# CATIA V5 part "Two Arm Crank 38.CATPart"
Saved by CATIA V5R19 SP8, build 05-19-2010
Part number: Two Arm Crank 38
Bounding box of the stored display mesh (mm): x -12.5 to 12.5, y 672.86 to 718.081, z 460.504 to 507.14
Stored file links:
  G:\EU_thinkMotion\CFAO_2010\MMS_groupe3\MMS_groupe3\A reprendre\fovide\fovide\Two Arm Crank 38.CATPart
  G:\EU_thinkMotion\CFAO_2010\MMS_groupe3\MMS_groupe3\A reprendre\fovide\fovide\fovide.CATProduct
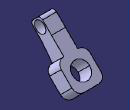
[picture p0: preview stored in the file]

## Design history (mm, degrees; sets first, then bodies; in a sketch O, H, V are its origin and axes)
Set1
  Plane1: linked copy from another document
  Point1 "Point.J": linked copy from another document
  Line1: linked copy from another document
  Line2: linked copy from another document
  Plane2: linked copy from another document
  Point2 "Point.L": linked copy from another document
Body1 (main body)
  Sketch1 on Plane1, origin (0, 590, 590), H (1, 0, 0), V (0, -0.7071, 0.7071)
    circle A1 centre (0, -162.6346) radius 7.5
    point P1 (0, -162.6346)
    reference projected point E1 (0, -162.6346) from Point1
    line L1 (-12.5, -150.1346) -> (12.5, -150.1346)
    line L2 (12.5, -150.1346) -> (12.5, -175.1346)
    line L3 (12.5, -175.1346) -> (-12.5, -175.1346)
    line L4 (-12.5, -175.1346) -> (-12.5, -150.1346)
    reference projected line E2 (0, -162.6346) -> (0, -127.2792) from Line1
    reference projected point E3 (0, -162.6346) from Point1
    radius A1 = 7.5
    length L2 = 25
    length L3 = 25
    distance L2 E2 = 12.5
    distance L1 E3 = 12.5
    coincidence: P1 E1
    horizontal: L1 H, L3 H
    vertical: L2 V, L4 V
  Pad1: profile Sketch1, direction (0, -0.7071, -0.7071), length 8, opposite side length 6
  Fillet1: radius 6, on edge [face of Pad1 from Sketch1.L2 | face of Pad1 from Sketch1.L3]; edge [face of Pad1 from Sketch1.L3 | face of Pad1 from Sketch1.L4]; edge [face of Pad1 from Sketch1.L1 | face of Pad1 from Sketch1.L2]; edge [face of Pad1 from Sketch1.L4 | face of Pad1 from Sketch1.L1]
  Sketch2 on Plane2, origin (0, 0, 0), H (0, 1, 0), V (0, 0, 1)
    point P1 (690.5043, 478.182)
    line L1 (690.5043, 478.182) -> (700.4038, 488.0815)
    point P2 (700.4038, 488.0815)
    line L2 (700.4038, 488.0815) -> (689.7972, 498.6881)
    point P3 (689.7972, 498.6881)
    line L3 (689.7972, 498.6881) -> (680, 508.4853)
    line L4 (680, 508.4853) -> (671.5147, 500)
    line L5 (671.5147, 500) -> (681.3119, 490.2028)
    point P6 (681.3119, 490.2028)
    line L6 (681.3119, 490.2028) -> (690.5043, 478.182)
    reference projected line E1 (700.4038, 488.0815) -> (690.5043, 478.182) from edge [face of Pad1 from Sketch1.L1 | face of Fillet1]
    reference projected point E2 (690.5043, 478.182) from vertex [face of Pad1 from Sketch1.L1 | end face of Pad1 | face of Fillet1]
    reference projected point E3 (700.4038, 488.0815) from vertex [face of Pad1 from Sketch1.L1 | start face of Pad1 | face of Fillet1]
    reference projected point E4 (680, 500) from Point2
    reference projected line E5 (705, 475) -> (680, 500) from Line1
    reference projected line E6 (705, 475) -> (680, 500) from Line1
    distance L4 E4 = 6
    distance P3 L1 = 15
    distance P6 L1 = 15
    length L4 = 12
    distance L3 E6 = 6
    parallelism: L4 L1, L5 L3, L3 E5
    coincidence: L1 E1, P1 E2, P2 E3
  Pad2: profile Sketch2, direction (1, 0, 0), length 6, mirrored extent
  Sketch3 on end face of Pad2, origin (6, 680, 500), H (0, 1, 0), V (0, 0, 1)
    point P1 (0, 0)
    intersected point E1 (0, 0) from Line2
    coincidence: E1 P1
  Hole1: placed by Sketch3, at (6, 680, 500) direction (-1, 0, 0), diameter 10, through (limit type 3)
  Fillet2: radius 3, on edge [face of Pad2 from Sketch2.L4 | face of Pad2 from Sketch2.L3]; edge [face of Pad2 from Sketch2.L5 | face of Pad2 from Sketch2.L4]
